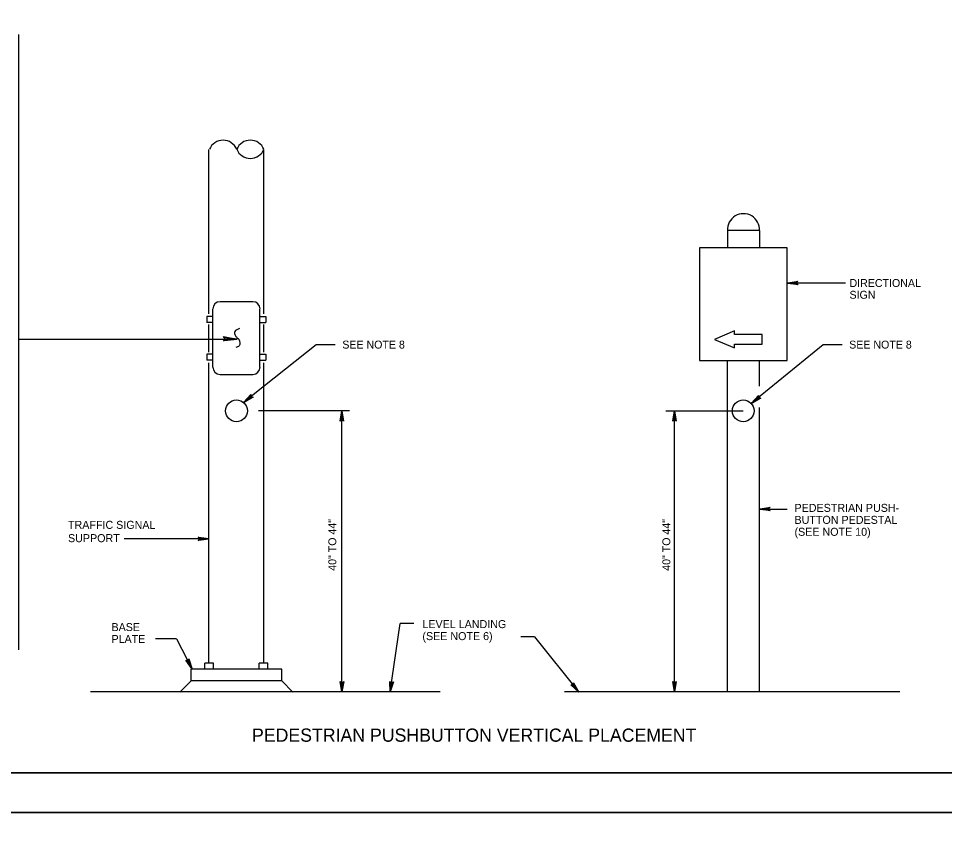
# Model space of a CAD drawing. Extents: x 36 to 940, y -1166 to 1210.
# Drawn here: x 262.3 to 612.2, y 608.7 to 916.3 of the extents above; entities that cross this region are included whole.
import ezdxf

# ---------------------------------------------------------------- set-up
doc = ezdxf.new("R2010")
doc.units = 0
for name, color, linetype in [('1', 7, 'Continuous'), ('2', 7, 'Continuous'), ('3', 7, 'Continuous'), ('Default', 7, 'Continuous'), ('PLT-BNDY', 7, 'Continuous')]:
    doc.layers.add(name, color=color, linetype=linetype)

# ---------------------------------------------------------------- blocks, each defined once
blk = doc.blocks.new('RARROW')
at = {"layer": '3'}
blk.add_lwpolyline([(-2.937125, 0.36875), (-2.82775, 0.156125), (0, 0), (-2.937125, 0.36875), (-3.08775, 0.497625), (0, 0), (-2.8255, -0.13975), (-2.928625, -0.350125), (0, 0), (-3.08775, -0.490625), (-2.928625, -0.350125)], dxfattribs=at)

msp = doc.modelspace()

# ---------------------------------------------------------------- linework, layer by layer
at = {"layer": '1'}
for p, q in [((861.86, 631.17), (75.86, 631.17)), ((75.86, 631.17), (661.86, 631.17))]:
    msp.add_line(p, q, dxfattribs=at)
at = {"layer": '2'}
for p, q in [((262.33, 910.3), (262.33, 677.76)), ((334.29, 804.68), (334.29, 866.81)), ((355.04, 804.68), (355.04, 866.81)), ((530.2, 836.15), (530.2, 829.69)), ((542.29, 836.15), (530.2, 836.15)), ((542.29, 836.15), (542.29, 829.69)), ((552.75, 829.69), (519.63, 829.69)), ((519.63, 829.69), (519.63, 787.1)), ((552.75, 787.1), (552.75, 829.69)), ((350.79, 809.18), (338.54, 809.18)), ((335.79, 784.43), (335.79, 806.43)), ((353.54, 784.43), (353.54, 806.43)), ((335.79, 803.68), (333.54, 803.68)), ((333.54, 803.68), (333.54, 801.43)), ((335.79, 801.43), (333.54, 801.43)), ((353.54, 803.68), (355.79, 803.68)), ((353.54, 801.43), (355.79, 801.43)), ((355.79, 803.68), (355.79, 801.43)), ((334.29, 790.18), (334.29, 800.68)), ((355.04, 790.18), (355.04, 800.68)), ((262.33, 795.18), (344.91, 795.18)), ((374.85, 792.99), (347.38, 771.15)), ((382, 792.99), (374.85, 792.99)), ((566.39, 792.99), (539.22, 770.78)), ((573.54, 792.99), (566.39, 792.99)), ((335.79, 789.43), (333.54, 789.43)), ((333.54, 789.43), (333.54, 787.18)), ((353.54, 789.43), (355.79, 789.43)), ((355.79, 789.43), (355.79, 787.18)), ((335.79, 787.18), (333.54, 787.18)), ((334.29, 672.68), (334.29, 786.18)), ((353.54, 787.18), (355.79, 787.18)), ((355.04, 672.68), (355.04, 786.18)), ((519.63, 787.1), (552.75, 787.1)), ((530.2, 661.81), (530.2, 787.1)), ((542.29, 777.32), (542.29, 787.1)), ((350.79, 781.68), (338.54, 781.68)), ((387.35, 768.04), (352.97, 768.04)), ((384.54, 661.81), (384.54, 768.04)), ((506.89, 768.04), (536.17, 768.04)), ((510.22, 661.81), (510.22, 768.04)), ((542.29, 661.81), (542.29, 769.34)), ((542.29, 730.92), (552.81, 730.92)), ((334.29, 719.66), (302.3, 719.66)), ((402.79, 661.81), (406.54, 687.68)), ((411.66, 687.68), (406.54, 687.68)), ((457.29, 682.61), (452.17, 682.61)), ((457.29, 682.61), (474.06, 661.71)), ((322.06, 681.88), (314.03, 681.88)), ((322.06, 681.88), (327.99, 670.43)), ((336.04, 672.68), (332.79, 672.68)), ((332.79, 670.43), (332.79, 672.68)), ((336.04, 670.43), (336.04, 672.68)), ((356.54, 672.68), (353.29, 672.68)), ((353.29, 670.43), (353.29, 672.68)), ((356.54, 670.43), (356.54, 672.68)), ((327.54, 665.93), (327.54, 670.43)), ((361.79, 670.43), (327.54, 670.43)), ((361.79, 665.93), (361.79, 670.43)), ((327.54, 665.93), (323.29, 661.68)), ((361.79, 665.93), (327.54, 665.93)), ((361.79, 665.93), (366.04, 661.68)), ((421.67, 661.81), (289.51, 661.81)), ((595.39, 661.81), (468.65, 661.81))]:
    msp.add_line(p, q, dxfattribs=at)
for points in [[(556.61, 815.86), (556.47, 816.14), (552.75, 816.34), (556.61, 815.86), (556.81, 815.69), (552.75, 816.34), (556.47, 816.52), (556.6, 816.8), (552.75, 816.34), (556.81, 816.99), (556.6, 816.8)], [(340.04, 795.81), (340.16, 795.43), (344.91, 795.18), (340.04, 795.81), (339.79, 796.18), (344.91, 795.18), (340.29, 794.93), (340.04, 794.56), (344.91, 795.18), (339.79, 794.43), (340.04, 794.56)], [(350.7, 773.17), (350.42, 773.3), (347.38, 771.15), (350.7, 773.17), (350.96, 773.16), (347.38, 771.15), (350.17, 773.6), (350.11, 773.9), (347.38, 771.15), (350.16, 774.18), (350.11, 773.9)], [(542.51, 772.84), (542.22, 772.97), (539.22, 770.78), (542.51, 772.84), (542.77, 772.84), (539.22, 770.78), (541.97, 773.27), (541.9, 773.57), (539.22, 770.78), (541.95, 773.84), (541.9, 773.57)], [(546.15, 730.44), (546, 730.72), (542.29, 730.92), (546.15, 730.44), (546.34, 730.27), (542.29, 730.92), (546, 731.11), (546.13, 731.38), (542.29, 730.92), (546.34, 731.57), (546.13, 731.38)], [(330.43, 720.14), (330.57, 719.86), (334.29, 719.66), (330.43, 720.14), (330.23, 720.31), (334.29, 719.66), (330.58, 719.47), (330.44, 719.2), (334.29, 719.66), (330.23, 719.01), (330.44, 719.2)], [(326.65, 674.08), (326.47, 673.83), (327.99, 670.43), (326.65, 674.08), (326.71, 674.34), (327.99, 670.43), (326.12, 673.64), (325.81, 673.64), (327.99, 670.43), (325.55, 673.74), (325.81, 673.64)], [(472.02, 665.02), (471.89, 664.74), (474.06, 661.71), (472.02, 665.02), (472.03, 665.28), (474.06, 661.71), (471.59, 664.49), (471.29, 664.42), (474.06, 661.71), (471.01, 664.47), (471.29, 664.42)]]:
    msp.add_lwpolyline(points, dxfattribs=at)
for centre, radius, start, end in [((339.61, 864.72), 5.59, 22.6622, 157.3378), ((349.92, 864.72), 5.59, 22.6622, 157.3378), ((349.92, 869.03), 5.59, 202.6622, 337.3378), ((338.5, 806.54), 2.75, 90, 180), ((350.87, 806.54), 2.75, 0, 90), ((338.5, 784.54), 2.75, 180, 270), ((350.87, 784.54), 2.75, 270, 0)]:
    msp.add_arc(centre, radius, start, end, dxfattribs=at)
msp.add_spline([(345.79, 799.18), (344.79, 798.68), (344.04, 798.06), (344.29, 796.43), (345.04, 795.56), (345.54, 795.06), (345.66, 792.56), (344.41, 791.93)], degree=3, dxfattribs=at)
at = {"layer": 'Default'}
msp.add_line((574.82, 816.34), (552.75, 816.34), dxfattribs=at)
msp.add_lwpolyline([(525.25, 795.03), (532.82, 791.82), (532.82, 793.23), (543.28, 793.23), (543.28, 796.83), (532.82, 796.83), (532.82, 798.24)], close=True, dxfattribs=at)
for centre in [(344.68, 768.04), (536.17, 768.04)]:
    msp.add_circle(centre, 4.11, dxfattribs=at)
msp.add_arc((536.25, 836.49), 6.06, 356.7918, 183.2082, dxfattribs=at)
at = {"layer": 'PLT-BNDY'}
for points in [[(35.86, 1210.17), (876.86, 1210.17), (876.86, 616.17), (35.86, 616.17)], [(35.86, 616.17), (876.86, 616.17), (876.86, 22.17), (35.86, 22.17)]]:
    msp.add_lwpolyline(points, close=True, dxfattribs=at)

# ---------------------------------------------------------------- block references
at = {"layer": '2', "xscale": 1.2574347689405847, "yscale": 1.3092961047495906}
for p, rotation in [((384.54, 768.04), 89.99999999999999), ((510.22, 768.04), 89.99999999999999), ((384.54, 661.81), -90.00000000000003), ((402.79, 661.81), -97.89944095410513), ((510.22, 661.81), -90.00000000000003)]:
    msp.add_blockref('RARROW', p, dxfattribs=dict(at, rotation=rotation))

# ---------------------------------------------------------------- texts
at = {"layer": '2'}
for s, height, p in [('DIRECTIONAL', 3, (576.32, 814.84)), ('SIGN', 3, (576.32, 810.4)), ('SEE NOTE 8', 3, (384.67, 791.57)), ('SEE NOTE 8', 3, (576.21, 791.57)), ('PEDESTRIAN PUSH-', 3.0248, (555.54, 729.85)), ('BUTTON PEDESTAL', 3.0248, (555.54, 725.32)), ('TRAFFIC SIGNAL', 3.0248, (281.03, 723.43)), ('SUPPORT', 3.025, (281.03, 718.4)), ('(SEE NOTE 10)', 3.0248, (555.54, 720.8)), ('BASE', 3, (297.49, 684.8)), ('LEVEL LANDING', 3.0248, (414.94, 685.91)), ('PLATE', 3, (297.49, 680.3)), ('(SEE NOTE 6)', 3.0248, (414.94, 681.38)), ('PEDESTRIAN PUSHBUTTON VERTICAL PLACEMENT', 5, (350.55, 642.96))]:
    msp.add_text(s, height=height, dxfattribs=at).set_placement(p)
for p in [(382.4, 707.58), (508.61, 707.58)]:
    msp.add_text('40" TO 44"', height=3, rotation=90, dxfattribs=at).set_placement(p)

doc.saveas('drawing.dxf')
